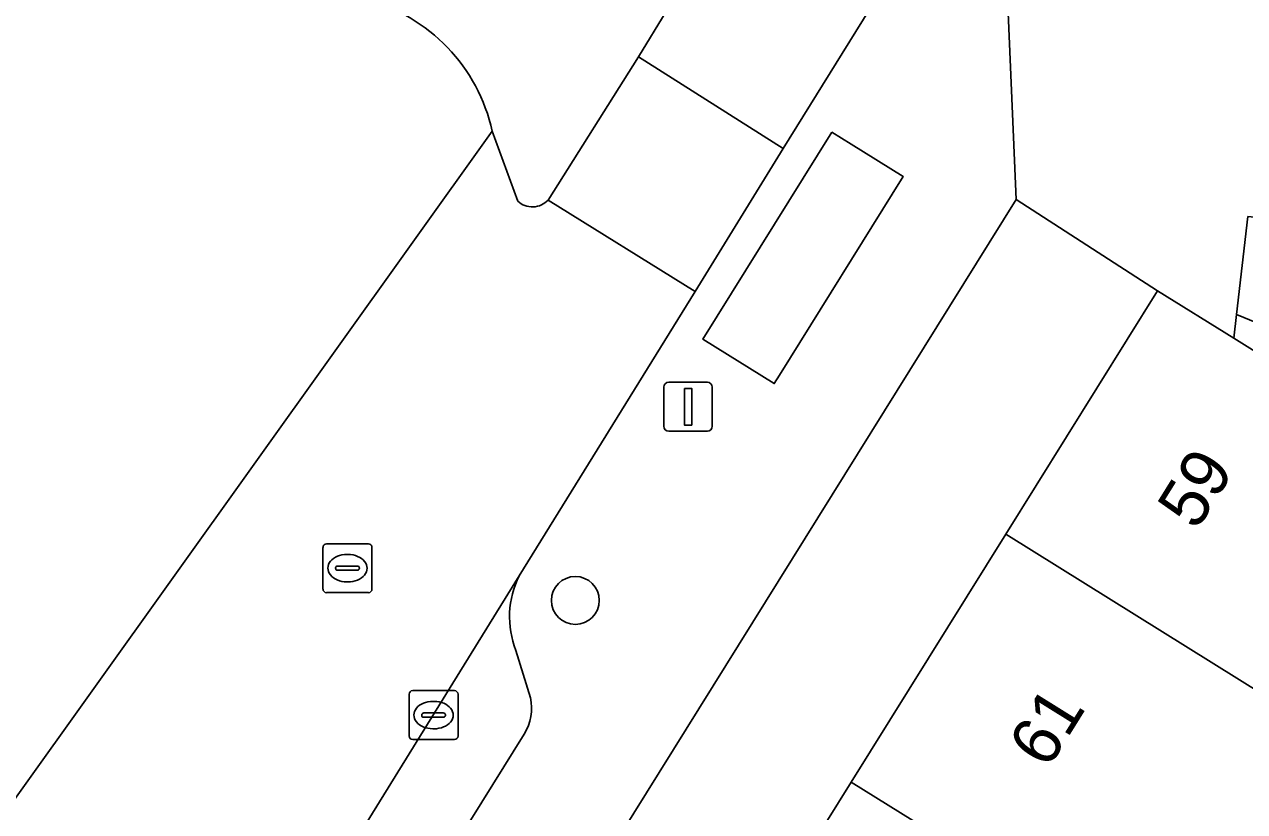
# Model space of a CAD drawing. Extents: x 160856 to 161310, y 384024 to 384878.
# Drawn here: x 161157.14 to 161182.07, y 384459.26 to 384475.34 of the extents above; entities that cross this region are included whole.
import ezdxf

# ---------------------------------------------------------------- set-up
doc = ezdxf.new("R2010")
doc.units = 0
for name, color, linetype in [('IMGEO_Boom', 7, 'Continuous'), ('IMGEO_Erf', 7, 'Continuous'), ('IMGEO_Kolk', 7, 'Continuous'), ('IMGEO_Lichtmast', 7, 'Continuous'), ('IMGEO_Pand', 7, 'Continuous'), ('IMGEO_Pand_nummerreeks', 7, 'Continuous'), ('IMGEO_Parkeervlak_open', 7, 'Continuous'), ('IMGEO_Rijbaan_lokaal_open', 7, 'Continuous'), ('IMGEO_Rioolput', 7, 'Continuous'), ('IMGEO_Voetpad_open', 7, 'Continuous')]:
    doc.layers.add(name, color=color, linetype=linetype)

msp = doc.modelspace()

# ---------------------------------------------------------------- linework, layer by layer
at = {"layer": 'IMGEO_Boom'}
msp.add_circle((161168.397, 384463.571), 0.489, dxfattribs=at)
at = {"layer": 'IMGEO_Erf'}
msp.add_lwpolyline([(161174.035, 384459.86), (161177.191, 384464.924), (161180.291, 384469.898), (161177.404, 384471.762), (161158.798, 384441.894), (161161.708, 384440.081), (161164.945, 384445.275), (161168.016, 384450.202), (161171.016, 384455.016)], close=True, dxfattribs=at)
msp.add_lwpolyline([(161201.269, 384461.906), (161197.618, 384463.448), (161197.448, 384463.045), (161181.905, 384469.413), (161181.848, 384468.928), (161184.535, 384467.253), (161186.64, 384465.941), (161183.54, 384460.968), (161180.384, 384455.904)], dxfattribs=at)
at = {"layer": 'IMGEO_Kolk'}
for p, q in [((161164.999, 384460.802), (161164.999, 384461.654)), ((161165.074, 384461.728), (161165.926, 384461.728)), ((161166, 384461.654), (161166, 384460.802)), ((161165.487, 384461.508), (161165.512, 384461.508)), ((161165.258, 384461.222), (161165.258, 384461.234)), ((161165.696, 384461.185), (161165.298, 384461.185)), ((161165.301, 384461.271), (161165.699, 384461.271)), ((161165.742, 384461.234), (161165.742, 384461.222)), ((161165.51, 384460.948), (161165.485, 384460.948)), ((161165.926, 384460.728), (161165.074, 384460.728))]:
    msp.add_line(p, q, dxfattribs=at)
for points in [[(161164.999, 384460.802), (161164.999, 384461.654)], [(161165.074, 384461.728), (161165.926, 384461.728)], [(161166, 384461.654), (161166, 384460.802)], [(161165.926, 384460.728), (161165.074, 384460.728)]]:
    msp.add_lwpolyline(points, dxfattribs=at)
for centre, radius, start, end in [((161165.076, 384461.652), 0.0765, 91.552, 178.448), ((161165.076, 384461.652), 0.0765, 91.552, 178.448), ((161165.924, 384461.652), 0.0765, 1.552, 88.448), ((161165.924, 384461.652), 0.0765, 1.552, 88.448), ((161165.298, 384461.231), 0.0403, 85.8775, 175.7526), ((161165.295, 384461.221), 0.0366, 178.938, 274.7102), ((161165.699, 384461.228), 0.043, 264.8664, 352.4533), ((161165.703, 384461.233), 0.0386, 1.7309, 96.639), ((161165.076, 384460.804), 0.0765, 181.552, 268.448), ((161165.076, 384460.804), 0.0765, 181.552, 268.448), ((161165.924, 384460.804), 0.0765, 271.552, 358.448), ((161165.924, 384460.804), 0.0765, 271.552, 358.448)]:
    msp.add_arc(centre, radius, start, end, dxfattribs=at)
for centre, major_axis, ratio, start_param, end_param in [((161165.486, 384461.228), (-0.387, 0.002), 0.722429, 4.712389, 7.853982), ((161165.511, 384461.228), (-0.39, 0.002), 0.717154, 1.570796, 4.712389)]:
    msp.add_ellipse(centre, major_axis=major_axis, ratio=ratio, start_param=start_param, end_param=end_param, dxfattribs=at)
at = {"layer": 'IMGEO_Lichtmast'}
for p, q in [((161170.204, 384467.13), (161170.204, 384467.93)), ((161170.204, 384467.93), (161170.204, 384467.13)), ((161170.304, 384468.03), (161171.094, 384468.03)), ((161171.094, 384468.03), (161170.304, 384468.03)), ((161171.194, 384467.93), (161171.194, 384467.13)), ((161171.194, 384467.13), (161171.194, 384467.93)), ((161171.094, 384467.03), (161170.304, 384467.03)), ((161170.304, 384467.03), (161171.094, 384467.03))]:
    msp.add_line(p, q, dxfattribs=at)
msp.add_lwpolyline([(161170.624, 384467.905), (161170.774, 384467.905), (161170.774, 384467.155), (161170.624, 384467.155), (161170.624, 384467.905)], dxfattribs=at)
for centre, start, end in [((161170.304, 384467.93), 90, 180), ((161170.304, 384467.93), 90, 180), ((161171.094, 384467.93), 0, 90), ((161171.094, 384467.93), 360, 90), ((161170.304, 384467.13), 180, 270), ((161170.304, 384467.13), 180, 270), ((161171.094, 384467.13), 270, 0), ((161171.094, 384467.13), 270, 0)]:
    msp.add_arc(centre, 0.1, start, end, dxfattribs=at)
at = {"layer": 'IMGEO_Pand'}
for points in [[(161177.191, 384464.924), (161183.54, 384460.968), (161186.64, 384465.941), (161184.535, 384467.253), (161181.848, 384468.928), (161180.291, 384469.898)], [(161177.191, 384464.924), (161174.035, 384459.86), (161180.384, 384455.904), (161183.54, 384460.968)], [(161180.384, 384455.904), (161174.035, 384459.86), (161171.016, 384455.016), (161177.365, 384451.06), (161179.472, 384449.748), (161182.49, 384454.592)]]:
    msp.add_lwpolyline(points, close=True, dxfattribs=at)
at = {"layer": 'IMGEO_Parkeervlak_open'}
msp.add_lwpolyline([(161173.638, 384473.141), (161171.003, 384468.91), (161172.461, 384468.002), (161172.57, 384468.176), (161175.097, 384472.232), (161174.034, 384472.894)], close=True, dxfattribs=at)
for points in [[(161167.25, 384464.077), (161162.091, 384455.73)], [(161167.478, 384461.584), (161167.182, 384462.55)], [(161160.463, 384449.774), (161167.352, 384460.84)]]:
    msp.add_lwpolyline(points, dxfattribs=at)
for centre, radius, start, end in [((161168.937, 384463.237), 1.884, 153.5207, 201.3797), ((161166.489, 384461.369), 1.012, 328.498, 12.2777)]:
    msp.add_arc(centre, radius, start, end, dxfattribs=at)
at = {"layer": 'IMGEO_Rijbaan_lokaal_open'}
for points in [[(161171.382, 384477.465), (161169.685, 384474.679), (161172.646, 384472.807), (161174.408, 384475.649), (161174.464, 384475.756)], [(161167.22, 384471.73), (161166.699, 384473.159), (161156.936, 384459.5), (161156.774, 384459.589), (161156.676, 384459.37), (161156.558, 384459.16), (161156.172, 384458.536), (161156.12, 384458.453), (161145.898, 384441.958), (161135.892, 384425.82), (161137.684, 384424.722), (161137.724, 384424.698), (161141.451, 384422.575), (161141.516, 384422.746), (161141.596, 384422.911), (161141.691, 384423.068), (161141.799, 384423.216), (161145.608, 384429.136), (161162.091, 384455.73)], [(161156.936, 384459.5), (161166.699, 384473.159)], [(161162.091, 384455.73), (161167.25, 384464.077), (161170.845, 384469.886), (161167.841, 384471.754)]]:
    msp.add_lwpolyline(points, dxfattribs=at)
msp.add_lwpolyline([(161172.646, 384472.807), (161169.685, 384474.679), (161167.841, 384471.754), (161170.845, 384469.886)], close=True, dxfattribs=at)
for centre, radius, start, end in [((161163.189, 384472.382), 3.595, 12.4754, 75.1404), ((161167.519, 384472.052), 0.439, 227.1946, 317.2319)]:
    msp.add_arc(centre, radius, start, end, dxfattribs=at)
at = {"layer": 'IMGEO_Rioolput'}
for p, q in [((161163.241, 384463.804), (161163.241, 384464.656)), ((161163.316, 384464.73), (161164.168, 384464.73)), ((161164.242, 384464.656), (161164.242, 384463.804)), ((161163.729, 384464.51), (161163.754, 384464.51)), ((161163.5, 384464.224), (161163.5, 384464.236)), ((161163.938, 384464.187), (161163.54, 384464.187)), ((161163.543, 384464.273), (161163.941, 384464.273)), ((161163.984, 384464.236), (161163.984, 384464.224)), ((161163.752, 384463.95), (161163.727, 384463.95)), ((161164.168, 384463.73), (161163.316, 384463.73))]:
    msp.add_line(p, q, dxfattribs=at)
for points in [[(161163.241, 384463.804), (161163.241, 384464.656)], [(161163.316, 384464.73), (161164.168, 384464.73)], [(161164.242, 384464.656), (161164.242, 384463.804)], [(161164.168, 384463.73), (161163.316, 384463.73)]]:
    msp.add_lwpolyline(points, dxfattribs=at)
for centre, radius, start, end in [((161163.318, 384464.654), 0.0765, 91.552, 178.448), ((161163.318, 384464.654), 0.0765, 91.552, 178.448), ((161164.166, 384464.654), 0.0765, 1.552, 88.448), ((161164.166, 384464.654), 0.0765, 1.552, 88.448), ((161163.54, 384464.233), 0.0403, 85.8775, 175.7526), ((161163.537, 384464.223), 0.0366, 178.938, 274.7102), ((161163.941, 384464.23), 0.043, 264.8664, 352.4533), ((161163.945, 384464.235), 0.0386, 1.7309, 96.639), ((161163.318, 384463.806), 0.0765, 181.552, 268.448), ((161163.318, 384463.806), 0.0765, 181.552, 268.448), ((161164.166, 384463.806), 0.0765, 271.552, 358.448), ((161164.166, 384463.806), 0.0765, 271.552, 358.448)]:
    msp.add_arc(centre, radius, start, end, dxfattribs=at)
for centre, major_axis, ratio, start_param, end_param in [((161163.728, 384464.23), (-0.387, 0.002), 0.722429, 4.712389, 7.853982), ((161163.753, 384464.23), (-0.39, 0.002), 0.717154, 1.570796, 4.712389)]:
    msp.add_ellipse(centre, major_axis=major_axis, ratio=ratio, start_param=start_param, end_param=end_param, dxfattribs=at)
at = {"layer": 'IMGEO_Voetpad_open'}
for points in [[(161167.841, 384471.754), (161169.685, 384474.679), (161171.382, 384477.465), (161171.432, 384477.588), (161171.471, 384477.715), (161171.498, 384477.845), (161171.514, 384477.977), (161171.518, 384478.11), (161171.51, 384478.242), (161171.49, 384478.373), (161171.459, 384478.502), (161171.416, 384478.628), (161171.365, 384478.743), (161166.462, 384479.274)], [(161177.165, 384477.339), (161177.404, 384471.762), (161180.291, 384469.898), (161181.848, 384468.928), (161181.905, 384469.413), (161182.138, 384471.416)], [(161177.404, 384471.762), (161177.165, 384477.339)], [(161174.464, 384475.756), (161174.408, 384475.649), (161172.646, 384472.807), (161170.845, 384469.886), (161167.25, 384464.077)], [(161166.699, 384473.159), (161167.22, 384471.73)], [(161158.798, 384441.894), (161177.404, 384471.762)], [(161201.473, 384463.351), (161197.078, 384464.867), (161189.071, 384468.147), (161189.545, 384470.658), (161187.113, 384470.907), (161182.138, 384471.416), (161181.905, 384469.413), (161197.448, 384463.045), (161197.618, 384463.448), (161201.269, 384461.906)], [(161167.182, 384462.55), (161167.478, 384461.584)], [(161167.352, 384460.84), (161160.463, 384449.774)]]:
    msp.add_lwpolyline(points, dxfattribs=at)
msp.add_lwpolyline([(161173.638, 384473.141), (161174.034, 384472.894), (161175.097, 384472.232), (161172.57, 384468.176), (161172.461, 384468.002), (161171.003, 384468.91)], close=True, dxfattribs=at)
for centre, radius, start, end in [((161163.189, 384472.382), 3.595, 12.4754, 75.1404), ((161167.519, 384472.052), 0.439, 227.1946, 317.2319), ((161168.937, 384463.237), 1.884, 153.5207, 201.3797), ((161166.489, 384461.369), 1.012, 328.498, 12.2777)]:
    msp.add_arc(centre, radius, start, end, dxfattribs=at)

# ---------------------------------------------------------------- texts
at = {"layer": 'IMGEO_Pand_nummerreeks'}
for s, p in [('59', (161181.089, 384464.977)), ('61', (161178.051, 384460.104))]:
    msp.add_text(s, height=1, rotation=58.0674, dxfattribs=at).set_placement(p)

doc.saveas('drawing.dxf')
